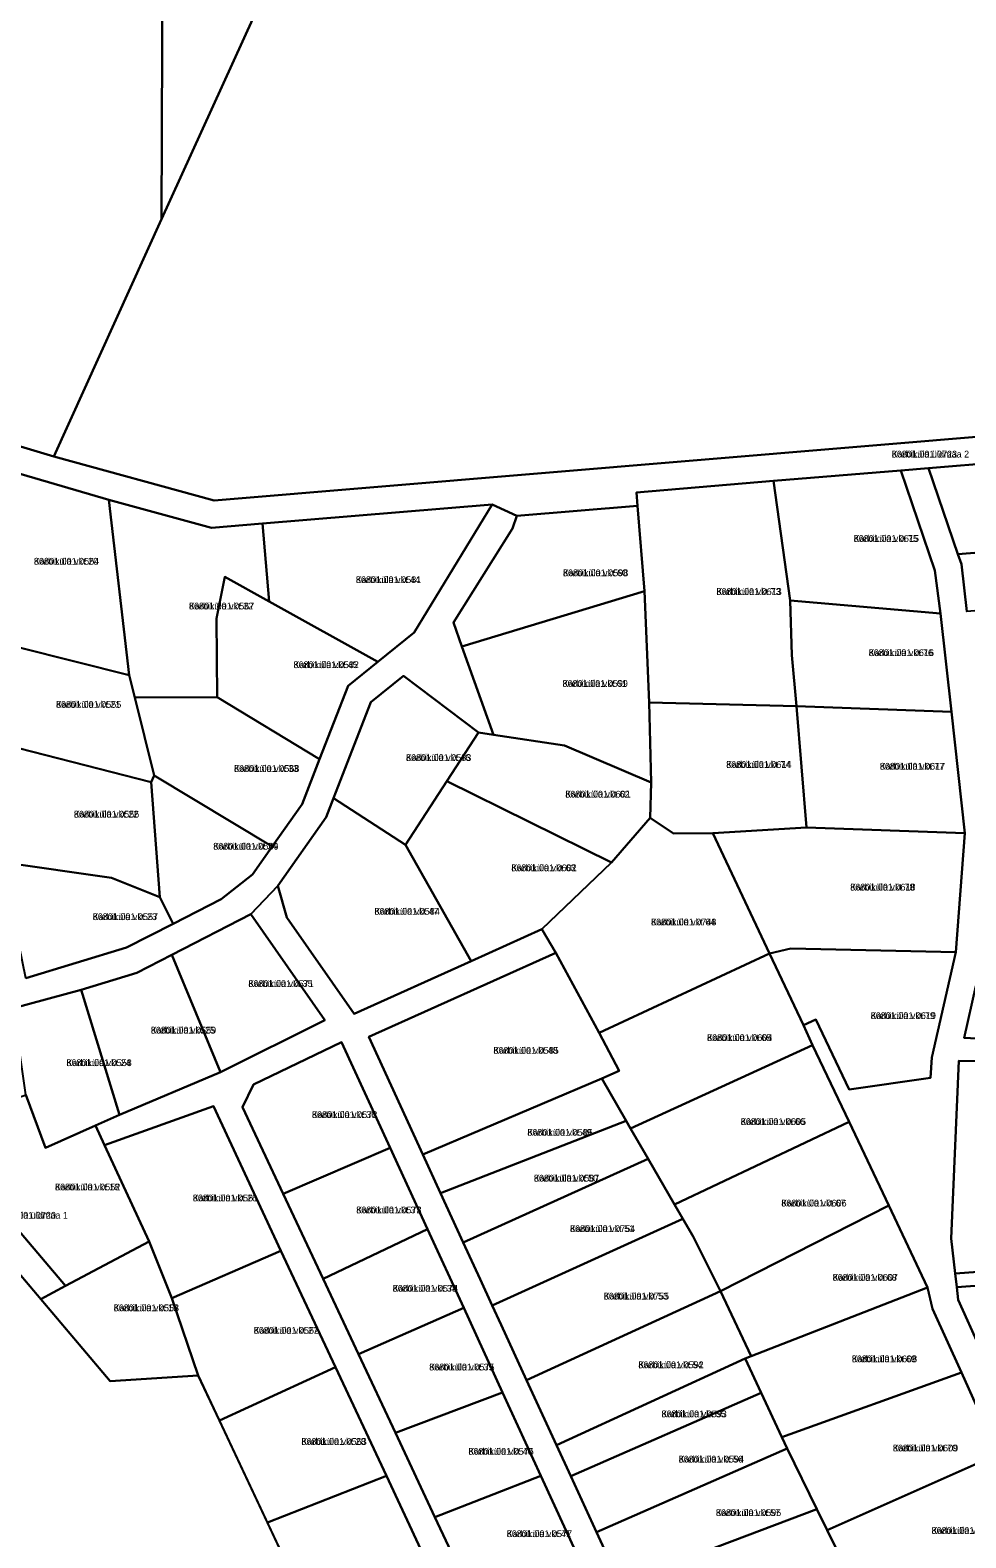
# Model space of a CAD drawing. Extents: x 484607 to 525396, y 6554521 to 6586559.
# Drawn here: x 516939.9 to 517147.5, y 6565291.3 to 6565625.8 of the extents above; entities that cross this region are included whole.
import ezdxf

# ---------------------------------------------------------------- set-up
doc = ezdxf.new("R2010")
doc.units = 0
for name, color, linetype in [('L_AADRESS', 7, 'Continuous'), ('PIIR', 7, 'Continuous'), ('TUNNUS', 7, 'Continuous')]:
    doc.layers.add(name, color=color, linetype=linetype)

msp = doc.modelspace()

# ---------------------------------------------------------------- linework, layer by layer
at = {"layer": 'PIIR'}
for points in [[(516624.51, 6565632.46), (516863.4, 6566170.69), (516868.78, 6566168.5), (516873.7, 6566179.49), (516891.5, 6566178.94), (517065.3, 6565905.83), (517021.69, 6565903.89), (516970.83, 6565902.01), (516969.2, 6565622.68), (516969.03, 6565583.85), (516945.1, 6565531.21), (516896.5, 6565545.83), (516879.03, 6565551.05), (516858.06, 6565557.72), (516855.91, 6565558.43), (516854.01, 6565562.38), (516843.12, 6565584.59), (516808.02, 6565591.89), (516759.59, 6565601.86), (516722.22, 6565619.19), (516611.88, 6565605.35)], [(517065.3, 6565905.83), (516891.5, 6566178.94), (516912.53, 6566178.83), (516942.14, 6566178.23), (517138.32, 6565871.47), (517164.4, 6565732.41), (517178.95, 6565654.98), (517194.19, 6565539.27), (516980.7, 6565521.48), (516945.1, 6565531.21), (516969.03, 6565583.85), (517062.63, 6565789.32)], [(516969.2, 6565622.68), (516970.83, 6565902.01), (517021.69, 6565903.89), (517065.3, 6565905.83), (517062.63, 6565789.32), (516969.03, 6565583.85)], [(516919.58, 6565532.61), (516957.33, 6565521.63), (516961.85, 6565482.69), (516925, 6565491.96)], [(517139.22, 6565528.66), (517171.3, 6565531.33), (517172.89, 6565511.73), (517145.75, 6565509.58)], [(517104.86, 6565525.8), (517133.05, 6565528.15), (517140.65, 6565505.96), (517141.92, 6565496.41), (517108.53, 6565499.29)], [(517074.39, 6565523.26), (517104.86, 6565525.8), (517108.53, 6565499.29), (517108.89, 6565487.15), (517109.92, 6565475.82), (517077.27, 6565476.67), (517076.22, 6565501.31), (517074.64, 6565520.27)], [(516957.33, 6565521.63), (516980.14, 6565515.41), (516991.44, 6565516.35), (516992.88, 6565499.06), (516983.09, 6565504.49), (516981.2, 6565495.29), (516981.41, 6565477.83), (516963.09, 6565477.72), (516961.85, 6565482.69)], [(516991.44, 6565516.35), (517042.42, 6565520.6), (517025.08, 6565492.2), (517017.04, 6565485.68), (516992.88, 6565499.06)], [(517047.88, 6565518.04), (517074.64, 6565520.27), (517076.22, 6565501.31), (517035.7, 6565489.05), (517033.8, 6565494.38), (517046.88, 6565515.22)], [(517145.75, 6565509.58), (517172.89, 6565511.73), (517173.95, 6565498.99), (517147.72, 6565496.8), (517146.52, 6565507.34)], [(516983.09, 6565504.49), (516992.88, 6565499.06), (517017.04, 6565485.68), (517010.45, 6565480.35), (517004.12, 6565464.05), (516981.41, 6565477.83), (516981.2, 6565495.29)], [(517035.7, 6565489.05), (517076.22, 6565501.31), (517077.27, 6565476.67), (517077.65, 6565458.91), (517058.45, 6565467.13), (517042.73, 6565469.45)], [(517108.53, 6565499.29), (517141.92, 6565496.41), (517144.33, 6565474.59), (517109.92, 6565475.82), (517108.89, 6565487.15)], [(516925, 6565491.96), (516961.85, 6565482.69), (516963.09, 6565477.72), (516967.39, 6565460.43), (516966.72, 6565458.96), (516928.57, 6565468.76)], [(517022.76, 6565482.57), (517039.35, 6565469.95), (517032.35, 6565459.16), (517023.19, 6565445.03), (517007.19, 6565455.4), (517015.46, 6565476.68)], [(516963.09, 6565477.72), (516981.41, 6565477.83), (517004.12, 6565464.05), (517000.24, 6565454.07), (516993.6, 6565444.65), (516967.39, 6565460.43)], [(517077.27, 6565476.67), (517109.92, 6565475.82), (517112.16, 6565448.9), (517091.34, 6565447.66), (517082.63, 6565447.59), (517077.48, 6565451.04), (517077.65, 6565458.91)], [(517109.92, 6565475.82), (517144.33, 6565474.59), (517147.3, 6565447.65), (517112.16, 6565448.9)], [(517039.35, 6565469.95), (517042.73, 6565469.45), (517058.45, 6565467.13), (517077.65, 6565458.91), (517077.48, 6565451.04), (517068.87, 6565441.16), (517032.35, 6565459.16)], [(516928.57, 6565468.76), (516966.72, 6565458.96), (516968.68, 6565433.45), (516957.9, 6565437.71), (516933.66, 6565441.24)], [(516967.39, 6565460.43), (516993.6, 6565444.65), (516989.24, 6565438.47), (516982.28, 6565433), (516971.63, 6565427.56), (516968.68, 6565433.45), (516966.72, 6565458.96)], [(517032.35, 6565459.16), (517068.87, 6565441.16), (517053.44, 6565426.38), (517037.72, 6565419.24), (517023.19, 6565445.03)], [(517007.19, 6565455.4), (517023.19, 6565445.03), (517037.72, 6565419.24), (517011.79, 6565407.58), (516996.82, 6565428.92), (516994.82, 6565435.98), (517005.56, 6565451.21)], [(517077.48, 6565451.04), (517082.63, 6565447.59), (517091.34, 6565447.66), (517103.97, 6565420.95), (517066.15, 6565403.32), (517056.55, 6565421.06), (517053.44, 6565426.38), (517068.87, 6565441.16)], [(517091.34, 6565447.66), (517112.16, 6565448.9), (517147.3, 6565447.65), (517145.29, 6565421.22), (517108.64, 6565422.05), (517103.97, 6565420.95)], [(516933.66, 6565441.24), (516957.9, 6565437.71), (516968.68, 6565433.45), (516971.63, 6565427.56), (516961.28, 6565422.26), (516938.89, 6565415.48)], [(516875.31, 6565430.66), (516891.78, 6565403.85), (516957.63, 6565326.08), (516977.18, 6565327.34), (517026.74, 6565221.86), (516558.37, 6564917.18), (516499.43, 6565116.04)], [(516971.31, 6565420.65), (516988.83, 6565429.64), (517005.27, 6565406.13), (516982.11, 6565394.6)], [(516951.18, 6565412.89), (516963.54, 6565416.68), (516971.31, 6565420.65), (516982.11, 6565394.6), (516959.69, 6565385.16)], [(517015.02, 6565402.45), (517056.55, 6565421.06), (517066.15, 6565403.32), (517070.6, 6565394.94), (517066.73, 6565393.24), (517027.02, 6565376.34)], [(517066.15, 6565403.32), (517103.97, 6565420.95), (517111.49, 6565405.05), (517113.46, 6565400.57), (517073.13, 6565382.11), (517072.13, 6565383.85), (517066.73, 6565393.24), (517070.6, 6565394.94)], [(517103.97, 6565420.95), (517108.64, 6565422.05), (517145.29, 6565421.22), (517139.98, 6565397.9), (517139.65, 6565393.34), (517121.59, 6565390.77), (517114.2, 6565406.33), (517111.49, 6565405.05)], [(517149.75, 6565413.79), (517179.33, 6565419.7), (517179.16, 6565400.54), (517147.12, 6565402.24)], [(516936.15, 6565408.79), (516951.18, 6565412.89), (516959.69, 6565385.16), (516954.35, 6565382.79), (516943.25, 6565377.84), (516938.95, 6565389.56)], [(516989.44, 6565391.84), (517008.96, 6565401.24), (517019.73, 6565377.82), (516996, 6565367.65), (516987, 6565386.82)], [(517073.13, 6565382.11), (517113.46, 6565400.57), (517121.64, 6565383.58), (517082.83, 6565365.24), (517076.98, 6565375.41)], [(517145.95, 6565397.1), (517164.22, 6565396.83), (517164.36, 6565376.38), (517164.54, 6565351.33), (517145.13, 6565349.92), (517144.23, 6565357.67)], [(517027.02, 6565376.34), (517066.73, 6565393.24), (517072.13, 6565383.85), (517030.96, 6565367.78)], [(516938.95, 6565389.56), (516943.25, 6565377.84), (516954.35, 6565382.79), (516956.38, 6565378.41), (516966.26, 6565357.06), (516947.72, 6565347.21), (516918.13, 6565382.06)], [(516956.38, 6565378.41), (516980.54, 6565387.08), (516995.54, 6565354.99), (516971.34, 6565344.44), (516966.26, 6565357.06)], [(517030.96, 6565367.78), (517072.13, 6565383.85), (517073.13, 6565382.11), (517076.98, 6565375.41), (517036, 6565356.82)], [(517082.83, 6565365.24), (517121.64, 6565383.58), (517130.41, 6565365.01), (517093.09, 6565346.04), (517086.98, 6565358.16), (517084.68, 6565362.08)], [(516996, 6565367.65), (517019.73, 6565377.82), (517028.05, 6565359.74), (517004.86, 6565348.77)], [(517036, 6565356.82), (517076.98, 6565375.41), (517082.83, 6565365.24), (517084.68, 6565362.08), (517042.42, 6565342.87), (517039.73, 6565348.7)], [(517093.09, 6565346.04), (517130.41, 6565365.01), (517139, 6565346.85), (517099.86, 6565331.63)], [(517004.86, 6565348.77), (517028.05, 6565359.74), (517036.08, 6565342.29), (517012.71, 6565332.06)], [(517042.42, 6565342.87), (517084.68, 6565362.08), (517086.98, 6565358.16), (517093.09, 6565346.04), (517050.05, 6565326.27), (517044.39, 6565338.57)], [(516966.26, 6565357.06), (516971.34, 6565344.44), (516977.18, 6565327.34), (516957.63, 6565326.08), (516942.21, 6565344.28), (516947.72, 6565347.21)], [(516971.34, 6565344.44), (516995.54, 6565354.99), (517007.62, 6565329.16), (516981.9, 6565317.3), (516977.18, 6565327.34)], [(517145.48, 6565346.94), (517182.85, 6565349.65), (517192.42, 6565328.46), (517165.51, 6565325.52), (517155.44, 6565322.76), (517145.81, 6565344.07)], [(517050.05, 6565326.27), (517093.09, 6565346.04), (517099.86, 6565331.63), (517098.52, 6565331.11), (517056.69, 6565311.83)], [(517098.52, 6565331.11), (517099.86, 6565331.63), (517139, 6565346.85), (517140.11, 6565342.13), (517146.51, 6565327.95), (517106.7, 6565313.65), (517102.09, 6565323.43)], [(517012.71, 6565332.06), (517036.08, 6565342.29), (517044.69, 6565323.56), (517020.92, 6565314.58)], [(516981.9, 6565317.3), (517007.62, 6565329.16), (517018.92, 6565305.01), (516992.53, 6565294.66)], [(517056.69, 6565311.83), (517098.52, 6565331.11), (517102.09, 6565323.43), (517059.86, 6565304.97)], [(517106.7, 6565313.65), (517146.51, 6565327.95), (517154.68, 6565309.84), (517116.74, 6565292.98), (517114.44, 6565297.64), (517107.88, 6565311.13)], [(517020.92, 6565314.58), (517044.69, 6565323.56), (517053.19, 6565305.08), (517029.7, 6565295.88)], [(517059.86, 6565304.97), (517102.09, 6565323.43), (517106.7, 6565313.65), (517107.88, 6565311.13), (517065.56, 6565292.58)], [(517065.56, 6565292.58), (517107.88, 6565311.13), (517114.44, 6565297.64), (517070.83, 6565281.12)], [(517116.74, 6565292.98), (517154.68, 6565309.84), (517162.82, 6565291.83), (517125.83, 6565274.49)], [(516992.53, 6565294.66), (517018.92, 6565305.01), (517030.63, 6565279.98), (517004.63, 6565268.92)], [(517029.7, 6565295.88), (517053.19, 6565305.08), (517061.41, 6565287.23), (517038.18, 6565277.82)], [(517070.83, 6565281.12), (517114.44, 6565297.64), (517116.74, 6565292.98), (517125.83, 6565274.49), (517079.71, 6565261.82)]]:
    msp.add_lwpolyline(points, close=True, dxfattribs=at)
for points in [[(516896.5, 6565545.83), (516945.1, 6565531.21), (516980.7, 6565521.48), (517194.19, 6565539.27)], [(517171.3, 6565531.33), (517139.22, 6565528.66), (517133.05, 6565528.15), (517104.86, 6565525.8), (517074.39, 6565523.26), (517074.64, 6565520.27), (517047.88, 6565518.04), (517042.42, 6565520.6), (516991.44, 6565516.35), (516980.14, 6565515.41), (516957.33, 6565521.63), (516919.58, 6565532.61)], [(517154.68, 6565309.84), (517146.51, 6565327.95), (517140.11, 6565342.13), (517139, 6565346.85), (517130.41, 6565365.01), (517121.64, 6565383.58), (517113.46, 6565400.57), (517111.49, 6565405.05), (517114.2, 6565406.33), (517121.59, 6565390.77), (517139.65, 6565393.34), (517139.98, 6565397.9), (517145.29, 6565421.22), (517147.3, 6565447.65), (517144.33, 6565474.59), (517141.92, 6565496.41), (517140.65, 6565505.96), (517133.05, 6565528.15), (517139.22, 6565528.66), (517145.75, 6565509.58), (517146.52, 6565507.34), (517147.72, 6565496.8)], [(516938.89, 6565415.48), (516961.28, 6565422.26), (516971.63, 6565427.56), (516982.28, 6565433), (516989.24, 6565438.47), (516993.6, 6565444.65), (517000.24, 6565454.07), (517004.12, 6565464.05), (517010.45, 6565480.35), (517017.04, 6565485.68), (517025.08, 6565492.2), (517042.42, 6565520.6), (517047.88, 6565518.04), (517046.88, 6565515.22), (517033.8, 6565494.38), (517035.7, 6565489.05), (517042.73, 6565469.45), (517039.35, 6565469.95), (517022.76, 6565482.57), (517015.46, 6565476.68), (517007.19, 6565455.4), (517005.56, 6565451.21), (516994.82, 6565435.98), (516988.83, 6565429.64), (516971.31, 6565420.65), (516963.54, 6565416.68), (516951.18, 6565412.89), (516936.15, 6565408.79)], [(517030.63, 6565279.98), (517018.92, 6565305.01), (517007.62, 6565329.16), (516995.54, 6565354.99), (516980.54, 6565387.08), (516956.38, 6565378.41), (516954.35, 6565382.79), (516959.69, 6565385.16), (516982.11, 6565394.6), (517005.27, 6565406.13), (516988.83, 6565429.64), (516994.82, 6565435.98), (516996.82, 6565428.92), (517011.79, 6565407.58), (517037.72, 6565419.24), (517053.44, 6565426.38), (517056.55, 6565421.06), (517015.02, 6565402.45), (517027.02, 6565376.34), (517030.96, 6565367.78), (517036, 6565356.82), (517039.73, 6565348.7), (517042.42, 6565342.87), (517044.39, 6565338.57), (517050.05, 6565326.27), (517056.69, 6565311.83), (517059.86, 6565304.97), (517065.56, 6565292.58), (517070.83, 6565281.12)], [(517149.75, 6565413.79), (517147.12, 6565402.24), (517179.16, 6565400.54)], [(516918.13, 6565382.06), (516947.72, 6565347.21), (516942.21, 6565344.28), (516891.78, 6565403.85)], [(517061.41, 6565287.23), (517053.19, 6565305.08), (517044.69, 6565323.56), (517036.08, 6565342.29), (517028.05, 6565359.74), (517019.73, 6565377.82), (517008.96, 6565401.24), (516989.44, 6565391.84), (516987, 6565386.82), (516996, 6565367.65), (517004.86, 6565348.77), (517012.71, 6565332.06), (517020.92, 6565314.58), (517029.7, 6565295.88), (517038.18, 6565277.82)], [(517164.22, 6565396.83), (517145.95, 6565397.1), (517144.23, 6565357.67), (517145.13, 6565349.92), (517145.48, 6565346.94), (517145.81, 6565344.07), (517155.44, 6565322.76)], [(517182.85, 6565349.65), (517145.48, 6565346.94), (517145.13, 6565349.92), (517164.54, 6565351.33)]]:
    msp.add_lwpolyline(points, dxfattribs=at)

# ---------------------------------------------------------------- texts
at = {"layer": 'L_AADRESS'}
for s, p in [('Karbiküla üldmaa 2', (517131.06, 6565531)), ('Karbiküla vkt 75', (517122.61, 6565512.28)), ('Karbiküla vkt 20', (516940.71, 6565507.23)), ('Karbiküla vkt 44', (517012.15, 6565503.14)), ('Karbiküla vkt 60', (517058.1, 6565504.66)), ('Karbiküla vkt 73', (517092.16, 6565500.51)), ('Karbiküla vkt 32', (516975.11, 6565497.29)), ('Karbiküla vkt 76', (517125.94, 6565486.94)), ('Karbiküla vkt 45', (516998.31, 6565484.27)), ('Karbiküla vkt 61', (517058.01, 6565480.11)), ('Karbiküla vkt 21', (516945.6, 6565475.46)), ('Karbiküla vkt 46', (517023.27, 6565463.67)), ('Karbiküla vkt 74', (517094.32, 6565462.13)), ('Karbiküla vkt 77', (517128.42, 6565461.74)), ('Karbiküla vkt 33', (516985.11, 6565461.24)), ('Karbiküla vkt 62', (517058.62, 6565455.55)), ('Karbiküla vkt 22', (516949.58, 6565451.11)), ('Karbiküla vkt 34', (516980.5, 6565443.99)), ('Karbiküla vkt 63', (517046.65, 6565439.2)), ('Karbiküla vkt 78', (517121.85, 6565434.92)), ('Karbiküla vkt 23', (516953.75, 6565428.36)), ('Karbiküla vkt 47', (517016.27, 6565429.55)), ('Karbiküla vkt 64', (517077.65, 6565427.18)), ('Karbiküla vkt 35', (516988.29, 6565413.52)), ('Karbiküla vkt 79', (517126.38, 6565406.41)), ('Karbiküla vkt 25', (516966.64, 6565403.18)), ('Karbiküla vkt 65', (517090.07, 6565401.53)), ('Karbiküla vkt 48', (517042.67, 6565398.7)), ('Karbiküla vkt 24', (516947.92, 6565395.96)), ('Karbiküla vkt 36', (517002.4, 6565384.44)), ('Karbiküla vkt 66', (517097.54, 6565382.9)), ('Karbiküla vkt 49', (517050.2, 6565380.51)), ('Karbiküla vkt 18', (516945.38, 6565368.38)), ('Karbiküla vkt 50', (517051.65, 6565370.34)), ('Karbiküla vkt 26', (516975.96, 6565365.95)), ('Karbiküla vkt 67', (517106.55, 6565364.81)), ('Karbiküla üldmaa 1', (516931.09, 6565362.11)), ('Karbiküla vkt 37', (517012.23, 6565363.29)), ('Karbiküla vkt 51', (517059.66, 6565359.14)), ('Karbiküla vkt 68', (517117.94, 6565348.32)), ('Karbiküla vkt 38', (517020.31, 6565345.9)), ('Karbiküla vkt 19', (516958.41, 6565341.57)), ('Karbiküla vkt 53', (517067.16, 6565344.17)), ('Karbiküla vkt 27', (516989.48, 6565336.57)), ('Karbiküla vkt 39', (517028.43, 6565328.43)), ('Karbiküla vkt 54', (517074.83, 6565328.93)), ('Karbiküla vkt 69', (517122.2, 6565330.25)), ('Karbiküla vkt 55', (517079.96, 6565318.04)), ('Karbiküla vkt 28', (517000.06, 6565311.91)), ('Karbiküla vkt 40', (517037.13, 6565309.72)), ('Karbiküla vkt 56', (517083.78, 6565308)), ('Karbiküla vkt 70', (517131.3, 6565310.46)), ('Karbiküla vkt 57', (517092.04, 6565296.12)), ('Karbiküla vkt 41', (517045.62, 6565291.45)), ('Karbiküla vkt 71', (517139.9, 6565292.16))]:
    msp.add_text(s, height=1.5, dxfattribs=at).set_placement(p)
at = {"layer": 'TUNNUS'}
for s, p in [('86801:001:0723', (517131.06, 6565531)), ('86801:001:0615', (517122.61, 6565512.28)), ('86801:001:0554', (516940.71, 6565507.23)), ('86801:001:0581', (517012.15, 6565503.14)), ('86801:001:0598', (517058.1, 6565504.66)), ('86801:001:0613', (517092.16, 6565500.51)), ('86801:001:0567', (516975.11, 6565497.29)), ('86801:001:0616', (517125.94, 6565486.94)), ('86801:001:0582', (516998.31, 6565484.27)), ('86801:001:0599', (517058.01, 6565480.11)), ('86801:001:0555', (516945.6, 6565475.46)), ('86801:001:0583', (517023.27, 6565463.67)), ('86801:001:0614', (517094.32, 6565462.13)), ('86801:001:0617', (517128.42, 6565461.74)), ('86801:001:0568', (516985.11, 6565461.24)), ('86801:001:0601', (517058.62, 6565455.55)), ('86801:001:0556', (516949.58, 6565451.11)), ('86801:001:0569', (516980.5, 6565443.99)), ('86801:001:0602', (517046.65, 6565439.2)), ('86801:001:0618', (517121.85, 6565434.92)), ('86801:001:0557', (516953.75, 6565428.36)), ('86801:001:0584', (517016.27, 6565429.55)), ('86801:001:0748', (517077.65, 6565427.18)), ('86801:001:0571', (516988.29, 6565413.52)), ('86801:001:0619', (517126.38, 6565406.41)), ('86801:001:0559', (516966.64, 6565403.18)), ('86801:001:0604', (517090.07, 6565401.53)), ('86801:001:0585', (517042.67, 6565398.7)), ('86801:001:0558', (516947.92, 6565395.96)), ('86801:001:0572', (517002.4, 6565384.44)), ('86801:001:0605', (517097.54, 6565382.9)), ('86801:001:0586', (517050.2, 6565380.51)), ('86801:001:0552', (516945.38, 6565368.38)), ('86801:001:0587', (517051.65, 6565370.34)), ('86801:001:0561', (516975.96, 6565365.95)), ('86801:001:0606', (517106.55, 6565364.81)), ('86801:001:0720', (516931.09, 6565362.11)), ('86801:001:0573', (517012.23, 6565363.29)), ('86801:001:0754', (517059.66, 6565359.14)), ('86801:001:0607', (517117.94, 6565348.32)), ('86801:001:0574', (517020.31, 6565345.9)), ('86801:001:0553', (516958.41, 6565341.57)), ('86801:001:0755', (517067.16, 6565344.17)), ('86801:001:0562', (516989.48, 6565336.57)), ('86801:001:0575', (517028.43, 6565328.43)), ('86801:001:0592', (517074.83, 6565328.93)), ('86801:001:0608', (517122.2, 6565330.25)), ('86801:001:0593', (517079.96, 6565318.04)), ('86801:001:0563', (517000.06, 6565311.91)), ('86801:001:0576', (517037.13, 6565309.72)), ('86801:001:0594', (517083.78, 6565308)), ('86801:001:0609', (517131.3, 6565310.46)), ('86801:001:0595', (517092.04, 6565296.12)), ('86801:001:0577', (517045.62, 6565291.45)), ('86801:001:0611', (517139.9, 6565292.16))]:
    msp.add_text(s, height=1.5, dxfattribs=at).set_placement(p)

doc.saveas('drawing.dxf')
